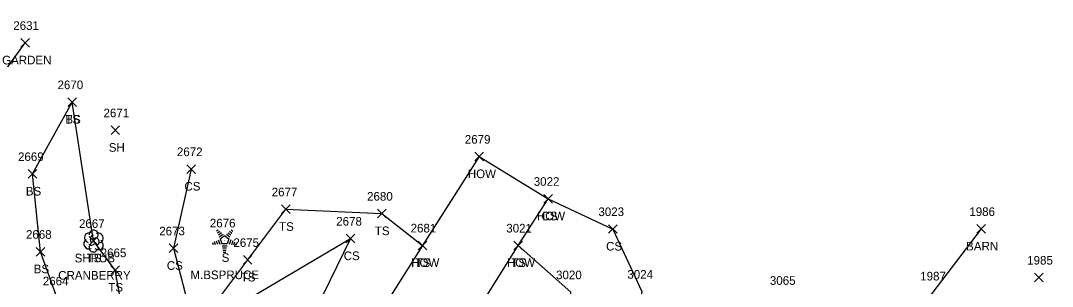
# Model space of a CAD drawing. Extents: x 1499292 to 1501024, y 534584 to 538043.
# Drawn here: x 1499668.2 to 1499907.3, y 537858.9 to 537920.6 of the extents above; entities that cross this region are included whole.
import ezdxf

# ---------------------------------------------------------------- set-up
doc = ezdxf.new("R2010")
doc.units = 0
for name, color, linetype in [('L_A', 7, 'Continuous'), ('L_C', 7, 'Continuous'), ('L_I', 7, 'Continuous'), ('L_TIC', 7, 'Continuous'), ('LAPB', 7, 'Continuous'), ('LBC', 7, 'Continuous'), ('LELB', 7, 'Continuous'), ('LSH', 7, 'Continuous'), ('LTC', 7, 'Continuous')]:
    doc.layers.add(name, color=color, linetype=linetype)

msp = doc.modelspace()

# ---------------------------------------------------------------- linework, layer by layer
at = {"layer": 'L_TIC'}
for points in [[(1499668.26, 537914.43), (1499670.26, 537916.43)], [(1499670.26, 537914.43), (1499668.26, 537916.43)], [(1499679.16, 537900.69), (1499681.16, 537902.69)], [(1499681.16, 537900.69), (1499679.16, 537902.69)], [(1499679.16, 537900.69), (1499681.16, 537902.69)], [(1499681.16, 537900.69), (1499679.16, 537902.69)], [(1499689.17, 537894.17), (1499691.17, 537896.17)], [(1499691.17, 537894.17), (1499689.17, 537896.17)], [(1499773.48, 537888.05), (1499775.48, 537890.05)], [(1499775.48, 537888.05), (1499773.48, 537890.05)], [(1499773.48, 537888.05), (1499775.48, 537890.05)], [(1499775.48, 537888.05), (1499773.48, 537890.05)], [(1499669.99, 537884.02), (1499671.99, 537886.02)], [(1499671.99, 537884.02), (1499669.99, 537886.02)], [(1499706.74, 537885.16), (1499708.74, 537887.16)], [(1499708.74, 537885.16), (1499706.74, 537887.16)], [(1499789.48, 537878.27), (1499791.48, 537880.27)], [(1499791.48, 537878.27), (1499789.48, 537880.27)], [(1499789.48, 537878.27), (1499791.48, 537880.27)], [(1499791.48, 537878.27), (1499789.48, 537880.27)], [(1499789.48, 537878.27), (1499791.48, 537880.27)], [(1499791.48, 537878.27), (1499789.48, 537880.27)], [(1499728.71, 537875.83), (1499730.71, 537877.83)], [(1499730.71, 537875.83), (1499728.71, 537877.83)], [(1499750.9, 537874.83), (1499752.9, 537876.83)], [(1499752.9, 537874.83), (1499750.9, 537876.83)], [(1499804.46, 537871.25), (1499806.46, 537873.25)], [(1499806.46, 537871.25), (1499804.46, 537873.25)], [(1499889.83, 537871.27), (1499891.83, 537873.27)], [(1499891.83, 537871.27), (1499889.83, 537873.27)], [(1499684.11, 537868.51), (1499686.11, 537870.51)], [(1499686.11, 537868.51), (1499684.11, 537870.51)], [(1499702.66, 537866.78), (1499704.66, 537868.78)], [(1499704.66, 537866.78), (1499702.66, 537868.78)], [(1499743.66, 537869.04), (1499745.66, 537871.04)], [(1499745.66, 537869.04), (1499743.66, 537871.04)], [(1499760.34, 537867.45), (1499762.34, 537869.45)], [(1499762.34, 537867.45), (1499760.34, 537869.45)], [(1499760.34, 537867.45), (1499762.34, 537869.45)], [(1499762.34, 537867.45), (1499760.34, 537869.45)], [(1499782.54, 537867.44), (1499784.54, 537869.44)], [(1499784.54, 537867.44), (1499782.54, 537869.44)], [(1499782.54, 537867.44), (1499784.54, 537869.44)], [(1499784.54, 537867.44), (1499782.54, 537869.44)], [(1499671.82, 537865.99), (1499673.82, 537867.99)], [(1499673.82, 537865.99), (1499671.82, 537867.99)], [(1499719.84, 537864.09), (1499721.84, 537866.09)], [(1499721.84, 537864.09), (1499719.84, 537866.09)], [(1499689.13, 537861.73), (1499691.13, 537863.73)], [(1499691.13, 537861.73), (1499689.13, 537863.73)], [(1499903.18, 537860), (1499905.18, 537862)], [(1499905.18, 537860), (1499903.18, 537862)]]:
    msp.add_lwpolyline(points, dxfattribs=at)
at = {"layer": 'LAPB'}
msp.add_lwpolyline([(1499652.79, 537920.59), (1499649.35, 537911.23), (1499660.23, 537903.01), (1499669.26, 537915.43)], dxfattribs=at)
at = {"layer": 'LBC'}
for points in [[(1499774.48, 537889.05), (1499761.34, 537868.45), (1499751.03, 537852.06), (1499733.05, 537823.72), (1499739.51, 537819.31), (1499747.5, 537814.24), (1499755.74, 537809.07), (1499763.85, 537820.93), (1499766.1, 537825.3), (1499759.01, 537829.06), (1499765.98, 537840.43), (1499768.74, 537844.8), (1499783.54, 537868.44), (1499790.48, 537879.27)], [(1499774.48, 537889.05), (1499790.48, 537879.27)], [(1499890.83, 537872.27), (1499879.39, 537857.32), (1499866.02, 537840.25), (1499845.24, 537856.3)]]:
    msp.add_lwpolyline(points, dxfattribs=at)
at = {"layer": 'LELB'}
for points in [[(1499684.49, 537825.81), (1499689.72, 537844.14), (1499676.72, 537856.18), (1499672.82, 537866.99), (1499670.99, 537885.02), (1499680.16, 537901.69)], [(1499703.02, 537844.01), (1499692.84, 537847.88), (1499690.13, 537862.73), (1499685.11, 537869.51), (1499680.16, 537901.69)], [(1499707.74, 537886.16), (1499703.66, 537867.78), (1499708.56, 537848.68), (1499744.66, 537870.04), (1499731.72, 537843.46), (1499723.52, 537829.45), (1499714.45, 537820.12), (1499721.62, 537803.53)], [(1499790.48, 537879.27), (1499805.46, 537872.25), (1499812.17, 537857.73), (1499807.76, 537835.31), (1499799.09, 537818.99), (1499788.73, 537811.11), (1499785.05, 537811.89)], [(1499708.56, 537848.68), (1499720.84, 537865.09), (1499729.71, 537876.83), (1499751.9, 537875.83), (1499761.34, 537868.45)], [(1499796.59, 537825.22), (1499794.34, 537844.01), (1499795.73, 537857.6), (1499783.54, 537868.44)]]:
    msp.add_lwpolyline(points, dxfattribs=at)
at = {"layer": 'LSH'}
msp.add_line((1499685.11, 537869.51), (1499685.11, 537869.51), dxfattribs=at)
msp.add_line((1499685.11, 537869.51), (1499685.11, 537869.51), dxfattribs=at)
msp.add_arc((1499685.15, 537870.94), 1.05, 335.5272, 180.9563, dxfattribs=at)
for centre, major_axis, ratio, start_param, end_param in [((1499684.32, 537870.17), (1.21, -0.51), 0.895232, 1.570796, 4.712389), ((1499686.15, 537870.09), (-1.14, -0.48), 0.949671, 1.570796, 4.712389), ((1499684.02, 537868.8), (0.58, -1.04), 0.959034, 3.141593, 6.283185), ((1499684.65, 537868.76), (-0.625, -0.083), 0.423636, 0, 3.141593), ((1499684.9, 537869.97), (-0.208, -0.792), 0.645439, 3.141593, 6.283185), ((1499685.61, 537869.34), (-0.5, 0.667), 0.989748, 3.141593, 6.283185), ((1499686.11, 537868.67), (-1.09, 0.79), 0.841452, 1.570796, 4.712389), ((1499685.11, 537868.01), (0.26, 1.06), 0.942809, 1.570796, 4.712389)]:
    msp.add_ellipse(centre, major_axis=major_axis, ratio=ratio, start_param=start_param, end_param=end_param, dxfattribs=at)
at = {"layer": 'LTC'}
for p, q in [((1499713.63, 537871.83), (1499713.98, 537872.09)), ((1499713.84, 537871.37), (1499714.36, 537871.75)), ((1499714.05, 537870.9), (1499714.75, 537871.41)), ((1499716.28, 537871.38), (1499716.96, 537870.88)), ((1499716.65, 537871.72), (1499717.2, 537871.32)), ((1499717.02, 537872.07), (1499717.44, 537871.77)), ((1499712.66, 537869.11), (1499712.81, 537868.64)), ((1499713.11, 537869.33), (1499713.33, 537868.68)), ((1499713.57, 537869.54), (1499713.84, 537868.71)), ((1499714.02, 537869.76), (1499714.36, 537868.74)), ((1499714.25, 537870.43), (1499715.13, 537871.07)), ((1499714.48, 537869.98), (1499715.49, 537870.71)), ((1499714.48, 537869.98), (1499714.87, 537868.79)), ((1499716.1, 537868.79), (1499714.87, 537868.79)), ((1499715.49, 537870.71), (1499716.49, 537869.99)), ((1499715.91, 537871.03), (1499716.72, 537870.44)), ((1499716.49, 537869.99), (1499716.1, 537868.79)), ((1499716.93, 537869.72), (1499716.59, 537868.68)), ((1499717.37, 537869.47), (1499717.08, 537868.58)), ((1499717.81, 537869.22), (1499717.58, 537868.49)), ((1499718.26, 537868.97), (1499718.07, 537868.39)), ((1499716.06, 537868.29), (1499714.91, 537868.29)), ((1499715.97, 537867.79), (1499714.99, 537867.79)), ((1499715.89, 537867.29), (1499715.06, 537867.29)), ((1499715.81, 537866.79), (1499715.13, 537866.79))]:
    msp.add_line(p, q, dxfattribs=at)

# ---------------------------------------------------------------- texts
at = {"layer": 'L_A'}
for s, p in [('GARDEN', (1499663.93, 537910.43)), ('TS', (1499678.57, 537896.69)), ('BS', (1499678.6, 537896.69)), ('SH', (1499688.65, 537890.17)), ('HOW', (1499771.86, 537884.05)), ('HOW', (1499771.86, 537884.05)), ('CS', (1499706.18, 537881.16)), ('BS', (1499669.43, 537880.02)), ('HOW', (1499787.87, 537874.27)), ('HOW', (1499787.87, 537874.27)), ('CS', (1499788.92, 537874.27)), ('TS', (1499728.12, 537871.83)), ('TS', (1499750.31, 537870.83)), ('CS', (1499803.9, 537867.25)), ('BARN', (1499887.34, 537867.27)), ('SHRUB', (1499680.74, 537864.51)), ('TS', (1499683.52, 537864.51)), ('S', (1499714.82, 537864.62)), ('CS', (1499743.1, 537865.04)), ('BS', (1499671.26, 537861.99)), ('CS', (1499702.1, 537862.78)), ('HOW', (1499758.73, 537863.45)), ('TS', (1499759.75, 537863.45)), ('HOW', (1499780.92, 537863.44)), ('TS', (1499781.95, 537863.44)), ('TS', (1499719.25, 537860.09)), ('TS', (1499688.54, 537857.73))]:
    msp.add_text(s, height=2, dxfattribs=at).set_placement(p)
at = {"layer": 'L_C'}
for s, p in [('CRANBERRY', (1499676.93, 537860.51)), ('M.BSPRUCE', (1499707.57, 537860.62))]:
    msp.add_text(s, height=2, dxfattribs=at).set_placement(p)
at = {"layer": 'L_I'}
for s, p in [('2631', (1499666.52, 537918.43)), ('2670', (1499676.77, 537904.69)), ('2670', (1499676.77, 537904.69)), ('2671', (1499687.43, 537898.17)), ('2679', (1499771.16, 537892.05)), ('2679', (1499771.16, 537892.05)), ('2672', (1499704.44, 537889.16)), ('2669', (1499667.62, 537888.02)), ('3022', (1499787.14, 537882.27)), ('3022', (1499787.14, 537882.27)), ('3022', (1499787.14, 537882.27)), ('2677', (1499726.41, 537879.83)), ('2680', (1499748.51, 537878.83)), ('3023', (1499802.12, 537875.25)), ('1986', (1499888.08, 537875.27)), ('2667', (1499681.75, 537872.51)), ('2667', (1499681.75, 537872.51)), ('2676', (1499712.07, 537872.62)), ('2678', (1499741.36, 537873.04)), ('2668', (1499669.46, 537869.99)), ('2673', (1499700.35, 537870.78)), ('2681', (1499758.6, 537871.45)), ('2681', (1499758.6, 537871.45)), ('3021', (1499780.77, 537871.44)), ('3021', (1499780.77, 537871.44)), ('2675', (1499717.53, 537868.09)), ('2665', (1499686.78, 537865.73)), ('1985', (1499901.49, 537864)), ('3020', (1499792.31, 537860.6)), ('3024', (1499808.83, 537860.73)), ('1987', (1499876.7, 537860.32)), ('2664', (1499673.37, 537859.18)), ('3065', (1499841.86, 537859.3))]:
    msp.add_text(s, height=2, dxfattribs=at).set_placement(p)
at = {"layer": 'LTC'}
msp.add_text('.', height=1.04, rotation=270, dxfattribs=at).set_placement((1499715.37, 537869.73))

doc.saveas('drawing.dxf')
